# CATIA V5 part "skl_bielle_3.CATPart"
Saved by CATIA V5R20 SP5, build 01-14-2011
Part number: skl_bielle_3
Publications: "Point.1", "Plan_ref", "Point.2", "Axe_pivot_bielle_4_bielle_2_3", "Axe_pivot_bielle_4_bati"
Bounding box of the stored display mesh (mm): x -10 to 10, y -90 to 0, z 100 to 100
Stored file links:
  U:\2A\IAO\ThinkMotion\skl_bielle_3.CATPart
  U:\2A\IAO\ThinkMotion\skl.CATProduct
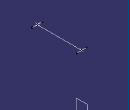
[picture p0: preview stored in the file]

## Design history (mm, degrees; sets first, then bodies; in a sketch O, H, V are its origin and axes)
Set1
  Point1: linked copy from another document
  Point2: linked copy from another document
  Plane1 "Plan_ref": linked copy from another document
Set2
  Line1: type PtPt, FirstPoint Point1, SecondPoint Point2
  Line2 "Axe_pivot_bielle_4_bielle_2_3": type Normal, RefPoint Point1, RefSkin Plane1, Start -10, End 10
  Line3 "Axe_pivot_bielle_4_bati": type Normal, RefPoint Point2, RefSkin Plane1, Start -10, End 10
Body1 (main body)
